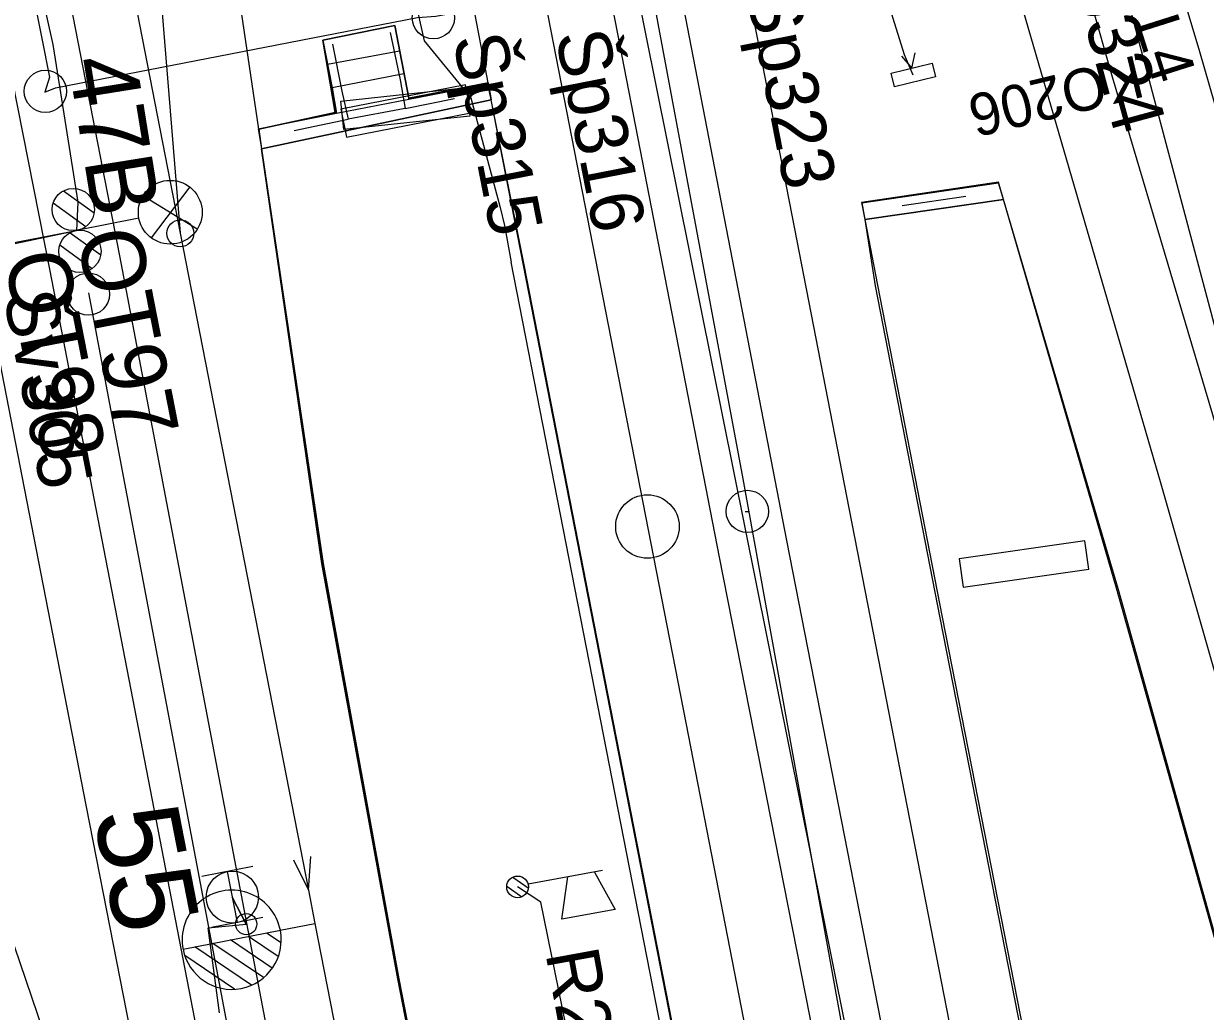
# Model space of a CAD drawing. Extents: x -545736 to -544888, y -1122892 to -1119128.
# Drawn here: x -545248.24 to -545220.32, y -1121645.11 to -1121621.77 of the extents above; entities that cross this region are included whole.
import ezdxf

# ---------------------------------------------------------------- set-up
doc = ezdxf.new("R2010")
doc.units = 0
for name, color, linetype in [('Podbarveni_Nastupiste', 7, 'Continuous'), ('Vrstva 1', 7, 'Continuous'), ('Vrstva 1 - Koleje', 7, 'Continuous'), ('Vrstva 11 - Trakce', 7, 'Continuous'), ('Vrstva 13', 7, 'Continuous'), ('Vrstva 14_zastreseni a nastupiste', 7, 'Continuous'), ('Vrstva 16_plochy', 7, 'Continuous'), ('Vrstva 17_ploty - zabradli', 7, 'Continuous'), ('Vrstva 19 - Staniceni', 7, 'Continuous'), ('Vrstva 2 - Vyhybky', 7, 'Continuous'), ('Vrstva 23 - PHS - pozemni - schody - eskalatory', 7, 'Continuous'), ('Vrstva 25', 7, 'Continuous'), ('Vrstva 26', 7, 'Continuous'), ('Vrstva 27', 7, 'Continuous'), ('Vrstva 28 - zabzar', 7, 'Continuous'), ('Vrstva 3 - Lisy - Pocitaci body', 7, 'Continuous'), ('Vrstva 31', 7, 'Continuous'), ('Vrstva 33 - prvky sdelzar', 7, 'Continuous'), ('Vrstva 4 - Teren - stezky - prechody - plochy', 7, 'Continuous'), ('Vrstva 43', 7, 'Continuous'), ('Vrstva 44', 7, 'Continuous'), ('Vrstva 6 - Navesti', 7, 'Continuous'), ('Vrstva 7 - Namezniky-vystroj', 7, 'Continuous')]:
    doc.layers.add(name, color=color, linetype=linetype)

msp = doc.modelspace()

# ---------------------------------------------------------------- linework, layer by layer
at = {"layer": 'Podbarveni_Nastupiste'}
for p, q in [((-545237.19, -1121623.577), (-545242.618, -1121624.735)), ((-545225.09, -1121625.931), (-545228.364, -1121626.398))]:
    msp.add_line(p, q, dxfattribs=at)
for points in [[(-545223.443, -1121694.09), (-545224.969, -1121686.265), (-545226.877, -1121676.484), (-545228.786, -1121666.678), (-545230.697, -1121656.879), (-545232.606, -1121647.081), (-545234.517, -1121637.287), (-545236.429, -1121627.481), (-545237.19, -1121623.577)], [(-545242.618, -1121624.735), (-545241.166, -1121634.527), (-545239.373, -1121644.341), (-545237.472, -1121654.104), (-545235.56, -1121663.904), (-545233.652, -1121673.703), (-545231.744, -1121683.481), (-545229.824, -1121693.33)], [(-545209.127, -1121693.444), (-545211.033, -1121683.652), (-545212.936, -1121673.863), (-545214.985, -1121664.112), (-545217.251, -1121654.384), (-545219.728, -1121644.713), (-545222.418, -1121635.111), (-545225.09, -1121625.931)], [(-545228.364, -1121626.398), (-545228.067, -1121627.952), (-545226.537, -1121635.795), (-545224.621, -1121645.607), (-545222.714, -1121655.377), (-545220.803, -1121665.19), (-545219.276, -1121673.043), (-545217.368, -1121682.822), (-545215.446, -1121692.657)]]:
    msp.add_lwpolyline(points, dxfattribs=at)
at = {"layer": 'Vrstva 1'}
msp.add_lwpolyline([(-545302.181, -1121474.436), (-545296.684, -1121502.424), (-545293.931, -1121513.189), (-545290.388, -1121524.236), (-545286.931, -1121533.793), (-545284.837, -1121539.457), (-545281.138, -1121549.394), (-545277.412, -1121559.403), (-545275.357, -1121564.997), (-545268.728, -1121583.293), (-545263.379, -1121599.198), (-545258.633, -1121613.308), (-545258.13, -1121614.806), (-545254.125, -1121626.758), (-545250.118, -1121638.716), (-545246.954, -1121648.017), (-545242.912, -1121659.983)], dxfattribs=at)
at = {"layer": 'Vrstva 1 - Koleje'}
for points in [[(-545253.234, -1121532.442), (-545253.081, -1121533.227), (-545252.417, -1121536.637), (-545250.056, -1121548.75), (-545248.704, -1121565.26), (-545248.321, -1121570.481), (-545247.86, -1121578.22), (-545247.334, -1121587.149), (-545247.195, -1121589.523), (-545247.09, -1121591.302), (-545246.823, -1121595.905), (-545246.563, -1121600.267), (-545246.275, -1121605.045), (-545245.888, -1121610.237), (-545244.538, -1121626.728), (-545241.512, -1121642.251), (-545241.359, -1121643.036)], [(-545253.234, -1121532.442), (-545253.081, -1121533.227), (-545252.417, -1121536.637), (-545250.056, -1121548.75), (-545246.877, -1121565.063), (-545245.498, -1121572.114), (-545243.946, -1121580.081), (-545242.319, -1121588.422), (-545241.158, -1121594.375), (-545240.981, -1121595.287), (-545240.164, -1121599.483), (-545238.848, -1121606.232), (-545237.423, -1121613.54), (-545235.54, -1121623.195), (-545234.061, -1121630.792), (-545232.534, -1121638.617), (-545230.963, -1121646.68), (-545229.074, -1121656.39), (-545227.16, -1121666.203), (-545225.219, -1121676.178), (-545223.305, -1121685.999), (-545221.784, -1121693.786)], [(-545248.408, -1121532.36), (-545248.259, -1121533.126), (-545247.475, -1121537.15), (-545244.429, -1121552.772), (-545240.225, -1121574.335), (-545238.879, -1121581.23), (-545237.501, -1121588.285), (-545235.953, -1121596.229), (-545234.349, -1121604.465), (-545232.932, -1121611.716), (-545232.152, -1121615.725), (-545231.632, -1121618.395), (-545230.091, -1121626.302), (-545228.735, -1121633.259), (-545226.244, -1121646.023), (-545224.344, -1121655.776), (-545222.446, -1121665.521), (-545220.908, -1121673.435), (-545219.01, -1121683.169), (-545217.101, -1121692.961)], [(-545262.808, -1121558.123), (-545261.44, -1121565.101), (-545259.605, -1121574.462), (-545255.964, -1121593.205), (-545254.16, -1121602.438), (-545251.631, -1121615.355), (-545251.074, -1121618.197), (-545250.782, -1121619.69), (-545249.671, -1121625.367), (-545248.119, -1121633.315), (-545246.758, -1121640.277), (-545245.328, -1121647.59), (-545243.775, -1121655.513), (-545242.406, -1121662.526), (-545240.503, -1121672.246), (-545240.152, -1121674.044), (-545239.735, -1121676.183), (-545238.49, -1121682.566), (-545236.691, -1121691.817), (-545233.508, -1121708.117), (-545230.481, -1121723.632), (-545230.326, -1121724.427)], [(-545249.218, -1121602.722), (-545248.63, -1121605.744), (-545247.716, -1121610.429), (-545244.538, -1121626.728), (-545241.512, -1121642.251), (-545241.359, -1121643.036)], [(-545225.616, -1121618.075), (-545225.108, -1121619.818), (-545223.546, -1121625.178), (-545221.373, -1121632.649), (-545218.975, -1121641.029), (-545216.466, -1121650.504), (-545215.616, -1121653.926), (-545213.339, -1121663.68), (-545211.292, -1121673.464), (-545209.393, -1121683.199), (-545207.488, -1121692.987)], [(-545241.359, -1121643.036), (-545240.78, -1121646.012), (-545240.207, -1121648.953)]]:
    msp.add_lwpolyline(points, dxfattribs=at)
at = {"layer": 'Vrstva 11 - Trakce'}
for p, q in [((-545247.298, -1121625.723), (-545246.575, -1121626.246)), ((-545247.54, -1121626.011), (-545246.772, -1121626.568)), ((-545254.71, -1121628.303), (-545246.988, -1121626.659)), ((-545247.142, -1121626.713), (-545246.417, -1121627.238)), ((-545247.382, -1121627.003), (-545246.616, -1121627.556))]:
    msp.add_line(p, q, dxfattribs=at)
for centre in [(-545247.067, -1121626.165), (-545246.909, -1121627.153)]:
    msp.add_circle(centre, 0.5, dxfattribs=at)
at = {"layer": 'Vrstva 13'}
for p, q in [((-545225.09, -1121625.931), (-545225.208, -1121625.521)), ((-545228.442, -1121626.001), (-545228.364, -1121626.398))]:
    msp.add_line(p, q, dxfattribs=at)
for points in [[(-545240.845, -1121623.887), (-545240.881, -1121623.876), (-545242.686, -1121624.268), (-545242.695, -1121624.261), (-545240.845, -1121623.887), (-545239.138, -1121623.558), (-545237.274, -1121623.195), (-545237.268, -1121623.173), (-545239.142, -1121623.538), (-545239.138, -1121623.558)], [(-545242.695, -1121624.261), (-545242.618, -1121624.735), (-545237.19, -1121623.577), (-545237.274, -1121623.195)], [(-545237.268, -1121623.173), (-545237.19, -1121623.577), (-545237.19, -1121623.577)], [(-545242.686, -1121624.268), (-545242.618, -1121624.735), (-545242.618, -1121624.735)], [(-545228.442, -1121626.001), (-545228.438, -1121626.008), (-545225.206, -1121625.531), (-545225.208, -1121625.521), (-545228.442, -1121626.001)], [(-545228.438, -1121626.008), (-545228.364, -1121626.398), (-545225.09, -1121625.931), (-545225.206, -1121625.531)], [(-545225.09, -1121625.931), (-545225.09, -1121625.931), (-545228.364, -1121626.398), (-545228.364, -1121626.398)]]:
    msp.add_lwpolyline(points, dxfattribs=at)
at = {"layer": 'Vrstva 14_zastreseni a nastupiste'}
for points in [[(-545229.851, -1121693.331), (-545231.771, -1121683.482), (-545233.679, -1121673.704), (-545235.587, -1121663.905), (-545237.499, -1121654.105), (-545239.4, -1121644.342), (-545241.193, -1121634.528), (-545242.618, -1121624.735), (-545242.618, -1121624.735), (-545237.19, -1121623.577), (-545237.19, -1121623.577)], [(-545223.426, -1121694.08), (-545224.952, -1121686.255), (-545226.86, -1121676.474), (-545228.769, -1121666.668), (-545230.68, -1121656.869), (-545232.589, -1121647.071), (-545234.5, -1121637.277), (-545236.412, -1121627.471), (-545237.19, -1121623.577), (-545242.618, -1121624.735)], [(-545223.443, -1121694.09), (-545224.969, -1121686.265), (-545226.877, -1121676.484), (-545228.786, -1121666.678), (-545230.697, -1121656.879), (-545232.606, -1121647.081), (-545234.517, -1121637.287), (-545236.429, -1121627.481), (-545237.19, -1121623.577)], [(-545229.824, -1121693.33), (-545231.744, -1121683.481), (-545233.652, -1121673.703), (-545235.56, -1121663.904), (-545237.472, -1121654.104), (-545239.373, -1121644.341), (-545241.166, -1121634.527), (-545242.618, -1121624.735)], [(-545225.09, -1121625.931), (-545225.09, -1121625.931), (-545228.364, -1121626.398), (-545228.364, -1121626.398), (-545228.12, -1121627.967), (-545226.59, -1121635.81), (-545224.674, -1121645.622), (-545222.767, -1121655.392), (-545220.856, -1121665.205), (-545219.329, -1121673.058), (-545217.421, -1121682.837), (-545215.499, -1121692.672)], [(-545209.083, -1121693.488), (-545210.989, -1121683.696), (-545212.892, -1121673.907), (-545214.941, -1121664.156), (-545217.207, -1121654.428), (-545219.684, -1121644.757), (-545222.374, -1121635.155), (-545225.09, -1121625.931), (-545228.364, -1121626.398)], [(-545209.127, -1121693.444), (-545211.033, -1121683.652), (-545212.936, -1121673.863), (-545214.985, -1121664.112), (-545217.251, -1121654.384), (-545219.728, -1121644.713), (-545222.418, -1121635.111), (-545225.09, -1121625.931)], [(-545228.364, -1121626.398), (-545228.067, -1121627.952), (-545226.537, -1121635.795), (-545224.621, -1121645.607), (-545222.714, -1121655.377), (-545220.803, -1121665.19), (-545219.276, -1121673.043), (-545217.368, -1121682.822), (-545215.446, -1121692.657)]]:
    msp.add_lwpolyline(points, dxfattribs=at)
at = {"layer": 'Vrstva 16_plochy'}
for points in [[(-545223.443, -1121694.09), (-545224.969, -1121686.265), (-545226.877, -1121676.484), (-545228.786, -1121666.678), (-545230.697, -1121656.879), (-545232.606, -1121647.081), (-545234.517, -1121637.287), (-545236.429, -1121627.481), (-545237.19, -1121623.577), (-545242.618, -1121624.735)], [(-545229.824, -1121693.33), (-545231.744, -1121683.481), (-545233.652, -1121673.703), (-545235.56, -1121663.904), (-545237.472, -1121654.104), (-545239.373, -1121644.341), (-545241.166, -1121634.527), (-545242.618, -1121624.735)], [(-545209.127, -1121693.444), (-545211.033, -1121683.652), (-545212.936, -1121673.863), (-545214.985, -1121664.112), (-545217.251, -1121654.384), (-545219.728, -1121644.713), (-545222.418, -1121635.111), (-545225.09, -1121625.931), (-545228.364, -1121626.398)], [(-545228.364, -1121626.398), (-545228.067, -1121627.952), (-545226.537, -1121635.795), (-545224.621, -1121645.607), (-545222.714, -1121655.377), (-545220.803, -1121665.19), (-545219.276, -1121673.043), (-545217.368, -1121682.822), (-545215.446, -1121692.657)]]:
    msp.add_lwpolyline(points, dxfattribs=at)
at = {"layer": 'Vrstva 17_ploty - zabradli'}
for p, q in [((-545239.223, -1121623.781), (-545238.058, -1121623.543)), ((-545239.223, -1121623.781), (-545240.573, -1121624.033)), ((-545241.844, -1121624.3), (-545240.573, -1121624.033)), ((-545227.482, -1121626.069), (-545225.983, -1121625.851))]:
    msp.add_line(p, q, dxfattribs=at)
for points in [[(-545239.582, -1121621.981), (-545239.344, -1121623.103), (-545239.223, -1121623.781)], [(-545240.939, -1121622.255), (-545240.723, -1121623.367), (-545240.573, -1121624.033)]]:
    msp.add_lwpolyline(points, dxfattribs=at)
at = {"layer": 'Vrstva 19 - Staniceni'}
msp.add_circle((-545233.502, -1121633.656), 0.75, dxfattribs=at)
at = {"layer": 'Vrstva 2 - Vyhybky'}
for p, q in [((-545242.175, -1121643.197), (-545241.359, -1121643.036)), ((-545244.473, -1121643.644), (-545242.174, -1121643.197)), ((-545242.224, -1121643.817), (-545242.927, -1121643.344)), ((-545242.157, -1121643.495), (-545242.504, -1121643.261)), ((-545244.473, -1121643.645), (-545244.473, -1121643.644)), ((-545242.856, -1121644.491), (-545244.193, -1121643.589)), ((-545242.572, -1121644.315), (-545243.771, -1121643.507)), ((-545242.365, -1121644.088), (-545243.349, -1121643.425)), ((-545243.256, -1121644.588), (-545244.43, -1121643.796))]:
    msp.add_line(p, q, dxfattribs=at)
for points in [[(-545247.716, -1121610.429), (-545244.538, -1121626.728), (-545241.512, -1121642.251), (-545241.359, -1121643.036)], [(-545245.888, -1121610.237), (-545244.538, -1121626.728)], [(-545241.863, -1121641.532), (-545241.512, -1121642.251), (-545241.457, -1121641.453)]]:
    msp.add_lwpolyline(points, dxfattribs=at)
msp.add_circle((-545244.538, -1121626.728), 0.32, dxfattribs=at)
for centre, radius, start, end in [((-545243.323, -1121643.419), 1.17, 10.9473, 191.4168), ((-545243.323, -1121643.421), 1.171, 191.0369, 10.9977)]:
    msp.add_arc(centre, radius, start, end, dxfattribs=at)
at = {"layer": 'Vrstva 23 - PHS - pozemni - schody - eskalatory'}
for p, q in [((-545239.257, -1121622.963), (-545240.949, -1121623.291)), ((-545240.845, -1121623.887), (-545240.881, -1121623.876))]:
    msp.add_line(p, q, dxfattribs=at)
for points in [[(-545240.881, -1121623.876), (-545241.173, -1121622.164), (-545239.467, -1121621.819), (-545239.142, -1121623.538)], [(-545239.467, -1121621.819), (-545239.257, -1121622.963), (-545239.138, -1121623.558)], [(-545241.173, -1121622.164), (-545240.949, -1121623.291), (-545240.845, -1121623.887)], [(-545239.357, -1121622.42), (-545241.058, -1121622.741)], [(-545240.845, -1121623.887), (-545239.138, -1121623.558), (-545239.142, -1121623.538)]]:
    msp.add_lwpolyline(points, dxfattribs=at)
for points in [[(-545237.77, -1121623.285), (-545237.698, -1121623.957), (-545240.677, -1121624.275), (-545240.749, -1121623.603)], [(-545237.673, -1121623.881), (-545237.802, -1121623.218), (-545240.743, -1121623.791), (-545240.614, -1121624.454)], [(-545226.137, -1121634.416), (-545226.041, -1121635.085), (-545223.075, -1121634.662), (-545223.171, -1121633.993)]]:
    msp.add_lwpolyline(points, close=True, dxfattribs=at)
at = {"layer": 'Vrstva 25'}
for p, q in [((-545244.316, -1121625.633), (-545245.229, -1121626.832)), ((-545244.137, -1121626.632), (-545245.421, -1121625.84)), ((-545245.516, -1121626.372), (-545246.988, -1121626.659)), ((-545248.46, -1121626.946), (-545246.988, -1121626.659))]:
    msp.add_line(p, q, dxfattribs=at)
msp.add_circle((-545244.775, -1121626.23), 0.754, dxfattribs=at)
at = {"layer": 'Vrstva 26'}
for points in [[(-545242.742, -1121604.753), (-545243.283, -1121605.165), (-545243.401, -1121605.297), (-545243.416, -1121605.962), (-545241.957, -1121608.062), (-545238.778, -1121622.18), (-545237.673, -1121623.527), (-545236.981, -1121626.119), (-545236.881, -1121626.541), (-545236.719, -1121627.411)], [(-545249.204, -1121614.896), (-545247.549, -1121622.269), (-545246.956, -1121625.995), (-545246.988, -1121626.659)], [(-545229.754, -1121663.065), (-545236.719, -1121627.411)]]:
    msp.add_lwpolyline(points, dxfattribs=at)
at = {"layer": 'Vrstva 27'}
for p, q in [((-545227.744, -1121622.949), (-545227.742, -1121622.945)), ((-545242.955, -1121643.048), (-545243.005, -1121643.052))]:
    msp.add_line(p, q, dxfattribs=at)
msp.add_lwpolyline([(-545227.5, -1121622.543), (-545227.259, -1121622.828), (-545227.176, -1121622.465)], dxfattribs=at)
msp.add_lwpolyline([(-545227.745, -1121622.946), (-545226.773, -1121622.71), (-545226.695, -1121623.034), (-545227.667, -1121623.27)], close=True, dxfattribs=at)
msp.add_circle((-545242.98, -1121643.05), 0.25, dxfattribs=at)
at = {"layer": 'Vrstva 28 - zabzar'}
for points in [[(-545227.22, -1121622.99), (-545227.43, -1121622.51), (-545228.69, -1121618.46), (-545229.44, -1121616.68), (-545229.78, -1121615.41), (-545229.55, -1121615.11), (-545229.77, -1121613.74)], [(-545222.23, -1121715.29), (-545222.21, -1121715.31), (-545221.11, -1121715.76), (-545219.32, -1121715.69), (-545215.16, -1121714.7), (-545215.49, -1121713.47), (-545218.48, -1121699.21), (-545219.11, -1121698), (-545219.09, -1121695.58), (-545224.77, -1121666.91), (-545226.14, -1121661.07), (-545228.34, -1121648.56), (-545231.24, -1121632.53), (-545233.58, -1121619.99), (-545234.02, -1121617.79), (-545229.44, -1121616.68)], [(-545243.61, -1121645.15), (-545243.88, -1121643.14), (-545242.98, -1121643.05), (-545243.31, -1121642.41), (-545242.98, -1121643.05)]]:
    msp.add_lwpolyline(points, dxfattribs=at)
at = {"layer": 'Vrstva 3 - Lisy - Pocitaci body'}
for p, q in [((-545242.822, -1121641.688), (-545244.032, -1121641.922)), ((-545243.427, -1121641.805), (-545243.193, -1121643.015)), ((-545242.588, -1121642.898), (-545243.798, -1121643.132))]:
    msp.add_line(p, q, dxfattribs=at)
msp.add_circle((-545243.309, -1121642.412), 0.616, dxfattribs=at)
at = {"layer": 'Vrstva 31'}
msp.add_lwpolyline([(-545222.21, -1121715.31), (-545222.21, -1121715.16), (-545222.31, -1121714.65), (-545222.63, -1121711.32), (-545224.86, -1121700.28), (-545225.44, -1121700), (-545225.1, -1121699.25), (-545229.08, -1121678.83), (-545229.58, -1121678.49), (-545229.26, -1121677.89), (-545231.4, -1121664.99), (-545233.57, -1121654.55), (-545236.02, -1121642.53), (-545236.57, -1121642.17)], dxfattribs=at)
at = {"layer": 'Vrstva 33 - prvky sdelzar'}
for p, q in [((-545236.684, -1121641.941), (-545236.317, -1121642.194)), ((-545234.561, -1121641.785), (-545236.321, -1121642.109)), ((-545235.521, -1121642.937), (-545235.379, -1121641.935)), ((-545234.75, -1121641.82), (-545234.262, -1121642.706)), ((-545236.825, -1121642.155), (-545236.466, -1121642.403)), ((-545234.262, -1121642.706), (-545235.521, -1121642.937))]:
    msp.add_line(p, q, dxfattribs=at)
msp.add_circle((-545236.57, -1121642.17), 0.256, dxfattribs=at)
at = {"layer": 'Vrstva 4 - Teren - stezky - prechody - plochy'}
for points in [[(-545238.257, -1121671.403), (-545239.603, -1121661.943), (-545241.087, -1121652.921), (-545245.969, -1121627.26), (-545251.871, -1121596.948), (-545256.698, -1121572.653), (-545262.46, -1121542.802), (-545267.421, -1121517.621), (-545274.826, -1121479.226), (-545286.689, -1121418.33), (-545287.291, -1121415.249)], [(-545238.257, -1121671.403), (-545239.204, -1121671.583), (-545242.78, -1121652.626), (-545247.617, -1121627.574), (-545253.657, -1121597.026), (-545258.256, -1121573.139), (-545263.497, -1121546.907), (-545269.153, -1121518.292), (-545274.888, -1121487.098), (-545276.507, -1121479.581), (-545277.637, -1121473.584), (-545277.381, -1121473.538), (-545288.106, -1121418.64), (-545288.328, -1121418.663), (-545288.974, -1121415.578)], [(-545242.686, -1121624.268), (-545240.881, -1121623.876), (-545241.173, -1121622.164), (-545239.467, -1121621.819), (-545239.142, -1121623.538), (-545237.268, -1121623.173), (-545242.374, -1121596.415), (-545245.26, -1121580.894), (-545246.292, -1121581.1)], [(-545242.686, -1121624.268), (-545243.555, -1121618.36), (-545244.509, -1121607.124), (-545245.127, -1121597.685), (-545246.292, -1121581.1)], [(-545230.058, -1121593.624), (-545229.255, -1121593.407), (-545223.205, -1121613.276), (-545220.476, -1121622.38), (-545217.216, -1121633.69), (-545214.01, -1121645.83), (-545211.204, -1121657.98), (-545206.59, -1121681.008), (-545202.547, -1121701.925)], [(-545230.058, -1121593.624), (-545227.825, -1121603.756), (-545225.054, -1121614.151), (-545222.526, -1121623.034), (-545219.417, -1121633.474), (-545215.613, -1121647.074), (-545212.994, -1121658.069), (-545207.784, -1121682.857), (-545204.102, -1121702.263)], [(-545157.45, -1122022.175), (-545154.783, -1122021.634), (-545154.868, -1122020.873), (-545158.409, -1122002.766), (-545161.985, -1121984.181), (-545167.947, -1121953.502), (-545173.012, -1121927.482), (-545183.259, -1121874.859), (-545192.216, -1121829.241), (-545202.384, -1121776.657), (-545211.092, -1121732.141), (-545220.696, -1121682.724), (-545230.205, -1121633.983), (-545237.607, -1121595.717), (-545239.248, -1121596.014)], [(-545157.45, -1122022.175), (-545157.217, -1122021.677), (-545160.795, -1122002.888), (-545164.002, -1121984.847), (-545169.404, -1121955.723), (-545174.573, -1121927.833), (-545184.757, -1121874.943), (-545193.65, -1121829.68), (-545203.839, -1121777.07), (-545212.63, -1121732.332), (-545221.738, -1121685.421), (-545231.797, -1121634.381), (-545239.248, -1121596.014)], [(-545223.426, -1121694.08), (-545224.952, -1121686.255), (-545226.86, -1121676.474), (-545228.769, -1121666.668), (-545230.68, -1121656.869), (-545232.589, -1121647.071), (-545234.5, -1121637.277), (-545236.412, -1121627.471), (-545237.19, -1121623.577), (-545237.268, -1121623.173), (-545239.142, -1121623.538), (-545239.467, -1121621.819), (-545241.173, -1121622.164), (-545240.881, -1121623.876), (-545242.686, -1121624.268), (-545242.618, -1121624.735), (-545241.193, -1121634.528), (-545239.4, -1121644.342), (-545237.499, -1121654.105), (-545235.587, -1121663.905), (-545233.679, -1121673.704), (-545231.771, -1121683.482), (-545229.851, -1121693.331)], [(-545209.083, -1121693.488), (-545210.989, -1121683.696), (-545212.892, -1121673.907), (-545214.941, -1121664.156), (-545217.207, -1121654.428), (-545219.684, -1121644.757), (-545222.374, -1121635.155), (-545225.09, -1121625.931), (-545225.208, -1121625.521), (-545228.442, -1121626.001), (-545228.364, -1121626.398), (-545228.12, -1121627.967), (-545226.59, -1121635.81), (-545224.674, -1121645.622), (-545222.767, -1121655.392), (-545220.856, -1121665.205), (-545219.329, -1121673.058), (-545217.421, -1121682.837), (-545215.499, -1121692.672)]]:
    msp.add_lwpolyline(points, dxfattribs=at)
at = {"layer": 'Vrstva 43'}
for centre in [(-545238.558, -1121621.634), (-545247.725, -1121623.372), (-545246.711, -1121628.165)]:
    msp.add_circle(centre, 0.5, dxfattribs=at)
at = {"layer": 'Vrstva 44'}
for points in [[(-545254.652, -1121587.661), (-545247.628, -1121623.038), (-545247.74, -1121623.395), (-545247.485, -1121623.293), (-545238.933, -1121621.629), (-545238.502, -1121621.598), (-545238.122, -1121621.525), (-545233.949, -1121620.55), (-545233.724, -1121620.432), (-545233.447, -1121620.369), (-545229.171, -1121619.576), (-545228.871, -1121619.558), (-545228.598, -1121619.483), (-545223.232, -1121618.331), (-545222.832, -1121618.218), (-545222.563, -1121618.228), (-545217.8, -1121617.408), (-545217.501, -1121617.32), (-545217.187, -1121617.189), (-545215.091, -1121616.201), (-545214.861, -1121616.079), (-545214.72, -1121616.007), (-545209.164, -1121611.407), (-545208.73, -1121611.156)], [(-545203.565, -1121700.334), (-545212.31, -1121658.192), (-545222.869, -1121618.503), (-545222.832, -1121618.218)], [(-545225.704, -1121660.962), (-545233.807, -1121620.679), (-545233.724, -1121620.432)], [(-545246.704, -1121628.131), (-545239.921, -1121664.03), (-545230.274, -1121712.788), (-545225.223, -1121737.288), (-545225.157, -1121737.961)]]:
    msp.add_lwpolyline(points, dxfattribs=at)
at = {"layer": 'Vrstva 7 - Namezniky-vystroj'}
msp.add_line((-545231.191, -1121633.299), (-545231.091, -1121633.299), dxfattribs=at)
msp.add_circle((-545231.141, -1121633.299), 0.5, dxfattribs=at)

# ---------------------------------------------------------------- texts
at = {"layer": 'Vrstva 11 - Trakce'}
msp.add_text('47B', height=1.6, rotation=279.1361, dxfattribs=at).set_placement((-545247.192, -1121622.642))
at = {"layer": 'Vrstva 2 - Vyhybky'}
msp.add_text('55', height=2, rotation=281.0173, dxfattribs=at).set_placement((-545246.594, -1121640.45))
at = {"layer": 'Vrstva 25'}
for s, p in [('OT97', (-545246.988, -1121626.756)), ('OT98', (-545248.709, -1121627.277))]:
    msp.add_text(s, height=1.5, rotation=281.0332, dxfattribs=at).set_placement(p)
at = {"layer": 'Vrstva 27'}
msp.add_text('KO206', height=1, rotation=193.6234, dxfattribs=at).set_placement((-545221.942, -1121622.512))
at = {"layer": 'Vrstva 33 - prvky sdelzar'}
msp.add_text('R201', height=1.25, rotation=280.3776, dxfattribs=at).set_placement((-545235.913, -1121643.74))
at = {"layer": 'Vrstva 43'}
for s, rotation, p in [('Šp324', 285.1553, (-545223.711, -1121619.777)), ('Šp323', 281.0323, (-545231.172, -1121621.012)), ('Šp315', 281.0323, (-545238.104, -1121622.116)), ('Šp316', 281.0323, (-545235.679, -1121622.035)), ('Šv305', 281.0323, (-545248.723, -1121628.191))]:
    msp.add_text(s, height=1.25, rotation=rotation, dxfattribs=at).set_placement(p)
at = {"layer": 'Vrstva 6 - Navesti'}
msp.add_text('L4', height=1.05, rotation=287.6104, dxfattribs=at).set_placement((-545222.002, -1121621.758))

doc.saveas('drawing.dxf')
